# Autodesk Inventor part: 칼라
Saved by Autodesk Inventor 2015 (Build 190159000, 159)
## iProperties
Created: 2026-05
Part Number: 칼라
Material: 일반
Document SubType Name: Modeling
Designer: 104
Density: 1 g/cm^3
Appearance: 기본값
Author: 104
Author: jhkim
Creation Date: 2026-04-27
Sending System: Autodesk Inventor 2027
Preprocessor: ST-DEVELOPER v20.1
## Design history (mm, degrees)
node "칼라1"
node "솔리드1"
node "기준1"
